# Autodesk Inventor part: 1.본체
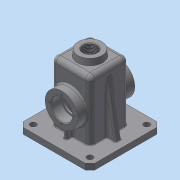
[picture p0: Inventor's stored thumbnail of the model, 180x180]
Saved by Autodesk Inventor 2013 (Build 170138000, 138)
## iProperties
Created: 2018-10
Part Number: 1.본체
Material: 일반
Document SubType Name: Modeling
Designer: Administrator
Density: 1 g/cm^3
Author: Administrator
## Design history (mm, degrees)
sketch "스케치1"
  geometry: L1 (-32.5, 32.5)-(32.5, 32.5); L2 (32.5, 32.5)-(32.5, -32.5); L3 (32.5, -32.5)-(-32.5, -32.5); L4 (-32.5, -32.5)-(-32.5, 32.5); L5 (-32.5, 32.5)-(32.5, -32.5); L6 (32.5, 32.5)-(-32.5, -32.5); 1 further point
  constraints: 12 end point, 2 midpoint, 2 parallel, 1 horizontal, 1 perpendicular
  dimensions: "d0" = 65 distance of L2.end L3.end; "d1" = 65 distance of L1.end L2.end
extrude "돌출1" new body sketch "스케치1" stored distance "d2" = 110; taper "d3" = 0 deg
fillet "모깎기1" dims "d4" = 8
fillet "모깎기2" dims "d5" = 8
feature "쉘1" dims "d6" = 5
sketch "스케치2"
  geometry: C1 r 27.5 at (24.5, 55); 1 further point
  constraints: 1 centre point, 1 coincident
  dimensions: "d7" = 55 diameter of C1
extrude "돌출2" join sketch "스케치2" distance "d8" = 15; taper "d9" = 0 deg
hole "구멍1" diameter "d12" = 30; stored, may be unused: countersink angle "d16" = 90 deg, drill point angle "d18" = 0 deg; dims "d10" = 10, "d11" = 10, "d13" = 6, "d14" = 35, "d15" = 17, "d17" = 8
sketch "스케치3"
  geometry: L1 (0, 0)-(0, 21); C1 r 27.5 at (0, 0) reference; 1 further point
  constraints: 2 end point, 1 coincident, 1 vertical
  dimensions: "d19" = 21 distance of L1.start L1.end
hole "구멍2" sketch "스케치3" at (0, 21) diameter "d20" = 3.242; stored, may be unused: countersink angle "d24" = 90 deg, drill point angle "d26" = 118 deg; dims "d21" = 8, "d22" = 35, "d23" = 17, "d25" = 10
node "작업 평면1"
sketch "스케치4"
  geometry: C1 r 20 at (0, 0); 1 further point
  constraints: 1 centre point, 1 coincident
  dimensions: "d31" = 40 diameter of C1
extrude "돌출3" join sketch "스케치4" stored distance "d32" = 15; taper "d33" = 7 deg
hole "구멍3" diameter "d36" = 22.835; stored, may be unused: countersink angle "d40" = 90 deg, drill point angle "d42" = 118 deg; dims "d34" = 10, "d35" = 10, "d37" = 30, "d38" = 35, "d39" = 17, "d41" = 10
sketch "스케치5"
  geometry: L1 (24.5, 32.5)-(-24.5, 32.5) reference; L2 (-32.5, 24.5)-(-32.5, -24.5) reference; L3 (-24.5, -32.5)-(24.5, -32.5) reference; L4 (32.5, -24.5)-(32.5, 24.5) reference; L5 (-60, 60)-(60, 60); L6 (60, 60)-(60, -60); L7 (60, -60)-(-60, -60); L8 (-60, -60)-(-60, 60); L9 (-60, 60)-(60, -60); L10 (60, 60)-(-60, -60); A1 r 8 centre (-24.5, 24.5) between (-24.5, 32.5) and (-32.5, 24.5) reference; A2 r 8 centre (-24.5, -24.5) between (-32.5, -24.5) and (-24.5, -32.5) reference; A3 r 8 centre (24.5, -24.5) between (24.5, -32.5) and (32.5, -24.5) reference; A4 r 8 centre (24.5, 24.5) between (32.5, 24.5) and (24.5, 32.5) reference; 1 further point
  constraints: 12 end point, 2 midpoint, 2 parallel, 1 horizontal, 1 perpendicular
  dimensions: "d43" = 120 distance of L6.end L7.end; "d44" = 120 distance of L5.end L6.end
extrude "돌출4" join sketch "스케치5" distance "d45" = 10; taper "d46" = 0 deg
chamfer "모따기1" distance "d47" = 8; stored, may be unused: second distance "d48" = 2, angle "d49" = 45 deg
sketch "스케치6"
  geometry: C1 r 5 at (-47.5, 47.5); C2 r 5 at (47.5, 47.5); C3 r 5 at (47.5, -47.5); C4 r 5 at (-47.5, -47.5); 1 further point
  constraints: 4 centre point
  dimensions: "d50" = 10 diameter of C1; "d51" = 10 diameter of C2; "d52" = 95 distance of C2.centre C1.centre; "d53" = 47.5 horizontal distance of C2.centre point (0, 0); "d54" = 47.5 horizontal distance of C2.centre point (0, 0); "d55" = 10 diameter of C3; "d56" = 10 diameter of C4; "d57" = 95 distance of C3.centre C4.centre; "d58" = 47.5 horizontal distance of C3.centre point (0, 0); "d59" = 95 distance of C3.centre C2.centre; "d60" = 95 distance of C1.centre C4.centre; "d61" = 47.5 horizontal distance of point (0, 0) C1.centre
extrude "돌출5" cut sketch "스케치6" stored distance "d62" = 10; taper "d63" = 0 deg
sketch "스케치7"
  geometry: L1 (-48, -45)-(-40.61, -3.09); L2 (20, 65)-(21.228, 55) reference; L3 (21.228, 55)-(24.5, 55) reference; L4 (32.5, 47)-(32.5, -45) reference; L5 (32.5, -45)-(60, -45) reference; L6 (60, -45)-(60, -55) reference; L7 (60, -55)-(27.5, -55) reference; L8 (27.5, -55)-(27.5, 47) reference; L9 (24.5, 50)-(11.418, 50) reference; L10 (11.418, 50)-(11.418, 65) reference; L11 (11.418, 65)-(20, 65) reference; L12 (-21.228, 55)-(-20, 65) reference; L13 (-20, 65)-(-11.418, 65) reference; L14 (-11.418, 65)-(-11.418, 50) reference; L15 (-11.418, 50)-(-24.5, 50) reference; L16 (-27.5, 47)-(-27.5, -55) reference; L17 (-27.5, -55)-(-60, -55) reference; L18 (-60, -55)-(-60, -45) reference; L19 (-60, -45)-(-32.5, -45) reference; L20 (-32.5, -45)-(-32.5, 47) reference; L21 (-24.5, 55)-(-21.228, 55) reference; A1 r 8 centre (24.5, 47) between (32.5, 47) and (24.5, 55) reference; A2 r 3 centre (24.5, 47) between (27.5, 47) and (24.5, 50) reference; A3 r 3 centre (-24.5, 47) between (-24.5, 50) and (-27.5, 47) reference; A4 r 8 centre (-24.5, 47) between (-24.5, 55) and (-32.5, 47) reference; 1 further point
  constraints: 2 end point, 1 point on line
  dimensions: "d64" = 12 distance from line of L1.start L18; "d65" = 10 deg angle of L1 L18
feature "리브1" sketch "스케치7" dims "d66" = 1, "d67" = 10, "d68" = 0, "d69" = 0, "d70" = 1, "d71" = 1
sketch "스케치8"
  geometry: L1 (-42.5, -45)-(-42.5, -27.5); L2 (36.526, -21)-(37.5, -22.621) reference; L3 (37.5, -22.621)-(47.5, -22.621) reference; L4 (47.5, -22.621)-(47.5, -27.5) reference; L5 (47.5, -27.5)-(32.5, -27.5) reference; L6 (32.5, -27.5)-(32.5, -45) reference; L7 (32.5, -45)-(60, -45) reference; L8 (60, -45)-(60, -55) reference; L9 (60, -55)-(27.5, -55) reference; L10 (27.5, -55)-(27.5, -15) reference; L11 (27.5, -15)-(30.5, -15) reference; L12 (30.5, -15)-(30.5, -17.5) reference; L13 (30.5, -17.5)-(47.5, -17.5) reference; L14 (47.5, -17.5)-(47.5, -19.379) reference; L15 (47.5, -19.379)-(37.5, -19.379) reference; L16 (37.5, -19.379)-(36.526, -21) reference; L17 (32.5, 27.5)-(47.5, 27.5) reference; L18 (47.5, 27.5)-(47.5, 22.621) reference; L19 (47.5, 22.621)-(37.5, 22.621) reference; L20 (37.5, 22.621)-(36.526, 21) reference; L21 (36.526, 21)-(37.5, 19.379) reference; L22 (37.5, 19.379)-(47.5, 19.379) reference; L23 (47.5, 19.379)-(47.5, 17.5) reference; L24 (47.5, 17.5)-(30.5, 17.5) reference; L25 (30.5, 17.5)-(30.5, 15) reference; L26 (30.5, 15)-(27.5, 15) reference; L27 (27.5, 15)-(27.5, 47) reference; L28 (24.5, 50)-(11.418, 50) reference; L29 (11.418, 50)-(11.418, 65) reference; L30 (11.418, 65)-(20, 65) reference; L31 (20, 65)-(21.228, 55) reference; L32 (21.228, 55)-(24.5, 55) reference; L33 (32.5, 47)-(32.5, 27.5) reference; L34 (-37.5, -22.621)-(-36.526, -21) reference; L35 (-36.526, -21)-(-37.5, -19.379) reference; L36 (-37.5, -19.379)-(-47.5, -19.379) reference; L37 (-47.5, -19.379)-(-47.5, -17.5) reference; L38 (-47.5, -17.5)-(-30.5, -17.5) reference; L39 (-30.5, -17.5)-(-30.5, -15) reference; L40 (-30.5, -15)-(-27.5, -15) reference; L41 (-27.5, -15)-(-27.5, -55) reference; L42 (-27.5, -55)-(-60, -55) reference; L43 (-60, -55)-(-60, -45) reference; L44 (-60, -45)-(-32.5, -45) reference; L45 (-32.5, -45)-(-32.5, -27.5) reference; L46 (-32.5, -27.5)-(-47.5, -27.5) reference; L47 (-47.5, -27.5)-(-47.5, -22.621) reference; L48 (-47.5, -22.621)-(-37.5, -22.621) reference; L49 (-47.5, 27.5)-(-32.5, 27.5) reference; L50 (-32.5, 27.5)-(-32.5, 47) reference; L51 (-24.5, 55)-(-21.228, 55) reference; L52 (-21.228, 55)-(-20, 65) reference; L53 (-20, 65)-(-11.418, 65) reference; L54 (-11.418, 65)-(-11.418, 50) reference; L55 (-11.418, 50)-(-24.5, 50) reference; L56 (-27.5, 47)-(-27.5, 15) reference; L57 (-27.5, 15)-(-30.5, 15) reference; L58 (-30.5, 15)-(-30.5, 17.5) reference; L59 (-30.5, 17.5)-(-47.5, 17.5) reference; L60 (-47.5, 17.5)-(-47.5, 19.379) reference; L61 (-47.5, 19.379)-(-37.5, 19.379) reference; L62 (-37.5, 19.379)-(-36.526, 21) reference; L63 (-36.526, 21)-(-37.5, 22.621) reference; L64 (-37.5, 22.621)-(-47.5, 22.621) reference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; A1 r 3 centre (24.5, 47) between (27.5, 47) and (24.5, 50) reference; A2 r 8 centre (24.5, 47) between (32.5, 47) and (24.5, 55) reference; A3 r 8 centre (-24.5, 47) between (-24.5, 55) and (-32.5, 47) reference; A4 r 3 centre (-24.5, 47) between (-24.5, 50) and (-27.5, 47) reference; 1 further point
  constraints: 2 end point, 2 point on line, 1 vertical
  dimensions: "d72" = 15 distance from line of L41.end L1
feature "리브2" sketch "스케치8" dims "d73" = 1, "d74" = 6, "d75" = 0, "d76" = 0, "d77" = 1, "d78" = 1
fillet "모깎기3" dims "d79" = 3
fillet "모깎기4" dims "d80" = 3
fillet "모깎기5" dims "d81" = 3
fillet "모깎기6" dims "d82" = 3
fillet "모깎기7" dims "d83" = 1
chamfer "모따기2" distance "d84" = 1; stored, may be unused: second distance "d85" = 2, angle "d86" = 45 deg
fillet "모깎기8" dims "d87" = 0.3
sketch "스케치10"
  geometry: L1 (57, 0)-(57, 91) reference; L2 (44.5, -18)-(4.5, -18) reference; 1 further point
  constraints: 1 other
  dimensions: "d88" = 32.5 distance from line of point (24.5, 8) L1; "d89" = 26 distance from line of point (24.5, 8) L2
feature "엠보싱1" sketch "스케치10" dims "d0" = 65, "d1" = 65, "d90" = 0.5, "d91" = 0
chamfer "모따기3" distance "d92" = 1; stored, may be unused: second distance "d93" = 2, angle "d94" = 45 deg
node "솔리드1"
pattern_circular "원형 패턴1" dims angle "d28" = 360 deg
mirror "대칭1"
mirror "대칭2"
mirror "대칭3"
node "절단 모서리 투영1"
node "절단 모서리 투영2"
other parameters: "d30" = 65
